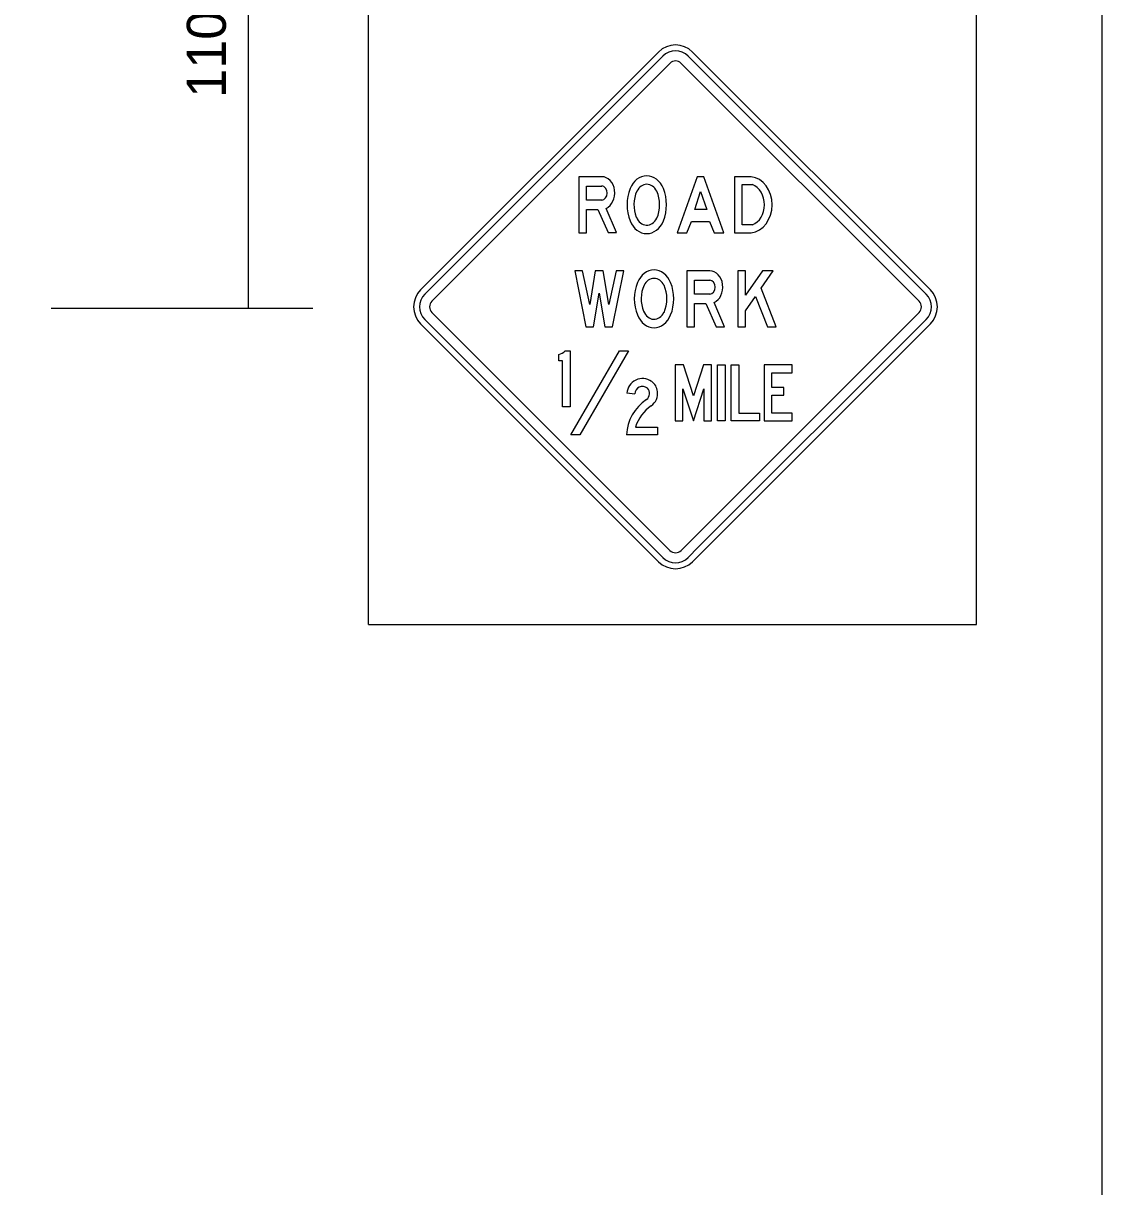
# Model space of a CAD drawing. Extents: x 21.7 to 29.1, y 5.9 to 16.2.
# Drawn here: x 27.437 to 29.094, y 7.653 to 9.44 of the extents above; entities that cross this region are included whole.
import ezdxf

# ---------------------------------------------------------------- set-up
doc = ezdxf.new("R2010")
doc.units = 0
for name, color, linetype in [('BORD-LINE', 7, 'Continuous'), ('C-SIGN-FACE-N', 7, 'Continuous'), ('DETL-DIMS', 7, 'Continuous'), ('DETL-LINE', 7, 'Continuous'), ('DETL-NOTE', 7, 'Continuous')]:
    doc.layers.add(name, color=color, linetype=linetype)

msp = doc.modelspace()

# ---------------------------------------------------------------- linework, layer by layer
at = {"layer": 'BORD-LINE'}
msp.add_lwpolyline([(21.7194, 16.2106), (29.0936, 16.2106), (29.0936, 5.8575), (21.7194, 5.8575)], close=True, dxfattribs=at)
at = {"layer": 'C-SIGN-FACE-N'}
for p, q in [((28.4129, 9.3962), (28.0475, 9.0309)), ((28.8304, 9.0309), (28.4651, 9.3962)), ((28.4915, 9.0242), (28.4915, 9.0242)), ((28.4129, 8.6133), (28.0475, 8.9787)), ((28.8304, 8.9787), (28.4651, 8.6133)), ((28.2596, 8.9216), (28.2596, 8.9314)), ((28.2596, 8.9216), (28.2596, 8.9314)), ((28.2596, 8.9216), (28.2596, 8.9314)), ((28.3763, 8.8708), (28.3642, 8.872)), ((28.3763, 8.8708), (28.3642, 8.872)), ((28.3763, 8.8708), (28.3642, 8.872)), ((28.3763, 8.8708), (28.3763, 8.8708)), ((28.3763, 8.8708), (28.3763, 8.8708)), ((28.3763, 8.8708), (28.3763, 8.8708)), ((28.4585, 8.6199), (28.474, 8.6354))]:
    msp.add_line(p, q, dxfattribs=at)
for points in [[(28.4194, 9.3897), (28.054, 9.0244)], [(28.8239, 9.0244), (28.4585, 9.3897)], [(28.0649, 9.0135), (28.4303, 9.3788)], [(28.4477, 9.3788), (28.813, 9.0135)], [(28.3256, 9.2047), (28.3022, 9.2047), (28.2906, 9.2047), (28.2906, 9.1186)], [(28.4913, 9.1359), (28.4985, 9.1186), (28.5133, 9.1186), (28.4823, 9.2047), (28.4723, 9.2047), (28.4413, 9.1186), (28.4562, 9.1186)], [(28.5552, 9.2047), (28.5295, 9.2047), (28.5295, 9.1186)], [(28.3256, 9.1688), (28.3022, 9.1688), (28.3022, 9.1903), (28.3256, 9.1903)], [(28.5414, 9.1307), (28.5414, 9.1925), (28.557, 9.1925)], [(28.2906, 9.1186), (28.3022, 9.1186), (28.3022, 9.1544), (28.3198, 9.1544), (28.3353, 9.1187)], [(28.3353, 9.1187), (28.3484, 9.1187), (28.3323, 9.1559)], [(28.4562, 9.1186), (28.4633, 9.1359), (28.4913, 9.1359)], [(28.5295, 9.1186), (28.5552, 9.1186)], [(28.557, 9.1307), (28.5414, 9.1307)], [(28.4915, 9.0601), (28.4681, 9.0601), (28.4565, 9.0601), (28.4565, 8.974)], [(28.4915, 9.0242), (28.4681, 9.0242), (28.4681, 9.0458), (28.4915, 9.0458)], [(28.4565, 8.974), (28.4681, 8.974), (28.4681, 9.0099), (28.4857, 9.0099), (28.5012, 8.9742), (28.5143, 8.9742), (28.4982, 9.0114)], [(28.4303, 8.6307), (28.0649, 8.9961)], [(28.813, 8.9961), (28.4477, 8.6307)], [(28.054, 8.9852), (28.4194, 8.6199)], [(28.474, 8.6354), (28.8239, 8.9852)], [(28.2694, 8.9371), (28.2773, 8.9371), (28.2773, 8.851), (28.2652, 8.851), (28.2652, 8.9216), (28.2596, 8.9216)], [(28.2694, 8.9371), (28.2773, 8.9371), (28.2773, 8.851), (28.2652, 8.851), (28.2652, 8.9216), (28.2596, 8.9216)], [(28.2694, 8.9371), (28.2773, 8.9371), (28.2773, 8.851), (28.2652, 8.851), (28.2652, 8.9216), (28.2596, 8.9216)], [(28.3775, 8.82), (28.4114, 8.82), (28.4114, 8.8079), (28.3636, 8.8079)], [(28.3775, 8.82), (28.4114, 8.82), (28.4114, 8.8079), (28.3636, 8.8079)], [(28.3775, 8.82), (28.4114, 8.82), (28.4114, 8.8079), (28.3636, 8.8079)], [(28.4585, 8.6199), (28.474, 8.6354)]]:
    msp.add_lwpolyline(points, dxfattribs=at)
for points in [[(28.4872, 9.1545), (28.4685, 9.1545), (28.4773, 9.182)], [(28.3595, 9.0601), (28.3477, 9.0601), (28.3364, 9.0085), (28.3281, 9.0601), (28.3157, 9.0601), (28.3073, 9.0085), (28.296, 9.0601), (28.2842, 9.0601), (28.3014, 8.974), (28.3132, 8.974), (28.3219, 9.0257), (28.3305, 8.974), (28.3423, 8.974)], [(28.5345, 8.974), (28.5463, 8.974), (28.5463, 8.9988), (28.5616, 9.0207), (28.5801, 8.974), (28.5937, 8.974), (28.5704, 9.0332), (28.5892, 9.0601), (28.5728, 9.0601), (28.5463, 9.0225), (28.5463, 9.0601), (28.5345, 9.0601)], [(28.3527, 8.9371), (28.3666, 8.9371), (28.2921, 8.8079), (28.2781, 8.8079)], [(28.3527, 8.9371), (28.3666, 8.9371), (28.2921, 8.8079), (28.2781, 8.8079)], [(28.3527, 8.9371), (28.3666, 8.9371), (28.2921, 8.8079), (28.2781, 8.8079)], [(28.4665, 8.8295), (28.4826, 8.879), (28.4826, 8.8295), (28.4944, 8.8295), (28.4944, 8.9156), (28.4819, 8.9156), (28.4665, 8.8679), (28.451, 8.9156), (28.4385, 8.9156), (28.4385, 8.8295), (28.4503, 8.8295), (28.4503, 8.879)], [(28.4665, 8.8295), (28.4826, 8.879), (28.4826, 8.8295), (28.4944, 8.8295), (28.4944, 8.9156), (28.4819, 8.9156), (28.4665, 8.8679), (28.451, 8.9156), (28.4385, 8.9156), (28.4385, 8.8295), (28.4503, 8.8295), (28.4503, 8.879)], [(28.4665, 8.8295), (28.4826, 8.879), (28.4826, 8.8295), (28.4944, 8.8295), (28.4944, 8.9156), (28.4819, 8.9156), (28.4665, 8.8679), (28.451, 8.9156), (28.4385, 8.9156), (28.4385, 8.8295), (28.4503, 8.8295), (28.4503, 8.879)], [(28.5036, 8.9156), (28.5154, 8.9156), (28.5154, 8.8295), (28.5036, 8.8295)], [(28.5036, 8.9156), (28.5154, 8.9156), (28.5154, 8.8295), (28.5036, 8.8295)], [(28.5036, 8.9156), (28.5154, 8.9156), (28.5154, 8.8295), (28.5036, 8.8295)], [(28.5246, 8.9156), (28.5364, 8.9156), (28.5364, 8.8415), (28.5678, 8.8415), (28.5678, 8.8295), (28.5246, 8.8295)], [(28.5246, 8.9156), (28.5364, 8.9156), (28.5364, 8.8415), (28.5678, 8.8415), (28.5678, 8.8295), (28.5246, 8.8295)], [(28.5246, 8.9156), (28.5364, 8.9156), (28.5364, 8.8415), (28.5678, 8.8415), (28.5678, 8.8295), (28.5246, 8.8295)], [(28.5869, 8.8415), (28.5869, 8.8691), (28.6055, 8.8691), (28.6055, 8.8811), (28.5869, 8.8811), (28.5869, 8.9035), (28.6183, 8.9035), (28.6183, 8.9156), (28.575, 8.9156), (28.575, 8.8295), (28.6183, 8.8295), (28.6183, 8.8415)], [(28.5869, 8.8415), (28.5869, 8.8691), (28.6055, 8.8691), (28.6055, 8.8811), (28.5869, 8.8811), (28.5869, 8.9035), (28.6183, 8.9035), (28.6183, 8.9156), (28.575, 8.9156), (28.575, 8.8295), (28.6183, 8.8295), (28.6183, 8.8415)], [(28.5869, 8.8415), (28.5869, 8.8691), (28.6055, 8.8691), (28.6055, 8.8811), (28.5869, 8.8811), (28.5869, 8.9035), (28.6183, 8.9035), (28.6183, 8.9156), (28.575, 8.9156), (28.575, 8.8295), (28.6183, 8.8295), (28.6183, 8.8415)]]:
    msp.add_lwpolyline(points, close=True, dxfattribs=at)
for centre, radius, start, end in [((28.439, 9.3701), 0.0369, 45, 135), ((28.439, 9.3701), 0.0277, 45, 135), ((28.439, 9.3701), 0.0123, 45, 135), ((28.0736, 9.0048), 0.0369, 135, 225), ((28.8043, 9.0048), 0.0369, 315, 45), ((28.0736, 9.0048), 0.0277, 135, 225), ((28.0736, 9.0048), 0.0123, 135, 225), ((28.8043, 9.0048), 0.0123, 315, 45), ((28.8043, 9.0048), 0.0277, 315, 45), ((28.253, 8.954), 0.0236, 286.2525, 314.1302), ((28.253, 8.954), 0.0236, 286.2525, 314.1302), ((28.253, 8.954), 0.0236, 286.2525, 314.1302), ((28.3883, 8.8705), 0.0241, 54.3694, 176.4795), ((28.3883, 8.8705), 0.0241, 54.3694, 176.4795), ((28.3883, 8.8705), 0.0241, 54.3694, 176.4795), ((28.3883, 8.8705), 0.012, 51.4666, 178.1909), ((28.3883, 8.8705), 0.012, 51.4666, 178.1909), ((28.3883, 8.8705), 0.012, 51.4666, 178.1909), ((28.391, 8.8735), 0.0201, 3.3316, 55.5862), ((28.391, 8.8735), 0.0201, 3.3316, 55.5862), ((28.391, 8.8735), 0.0201, 3.3316, 55.5862), ((28.3876, 8.8717), 0.0116, 306.1354, 44.8873), ((28.3876, 8.8717), 0.0116, 306.1354, 44.8873), ((28.3876, 8.8717), 0.0116, 306.1354, 44.8873), ((28.3899, 8.8709), 0.0215, 302.9934, 10.0902), ((28.3899, 8.8709), 0.0215, 302.9934, 10.0902), ((28.3899, 8.8709), 0.0215, 302.9934, 10.0902), ((28.4334, 8.8043), 0.0699, 123.8618, 177.0151), ((28.4334, 8.8043), 0.0699, 123.8618, 177.0151), ((28.4334, 8.8043), 0.0699, 123.8618, 177.0151), ((28.4384, 8.8006), 0.0639, 125.1387, 162.3655), ((28.4384, 8.8006), 0.0639, 125.1387, 162.3655), ((28.4384, 8.8006), 0.0639, 125.1387, 162.3655), ((28.439, 8.6394), 0.0277, 225, 315), ((28.439, 8.6394), 0.0123, 225, 315), ((28.439, 8.6394), 0.0369, 225, 315)]:
    msp.add_arc(centre, radius, start, end, dxfattribs=at)
for centre, major_axis, ratio, start_param, end_param in [((28.3253, 9.1796), (0, 0.0251), 0.813368, 3.487455, 6.269262), ((28.3948, 9.1711), (0, 0.0349), 0.812335, 5.167056, 7.399315), ((28.552, 9.1616), (0, 0.0432), 0.818392, 3.232708, 6.192058), ((28.3253, 9.1796), (0, 0.0108), 0.813368, 3.174143, 6.250457), ((28.4092, 9.1616), (0, 0.0549), 0.812335, 1.101522, 2.04007), ((28.3948, 9.1711), (0, 0.0219), 0.812335, 5.251232, 7.315139), ((28.3805, 9.1616), (0, 0.0549), 0.812335, 4.243115, 5.181663), ((28.5491, 9.1616), (0, 0.0324), 0.818392, 3.446507, 5.978271), ((28.4092, 9.1616), (0, 0.042), 0.812335, 1.053076, 2.040122), ((28.3805, 9.1616), (0, 0.042), 0.812335, 4.194619, 5.230159), ((28.3948, 9.1521), (0, 0.0349), 0.812335, 2.025463, 3.141593), ((28.3948, 9.1521), (0, 0.0219), 0.812335, 2.025521, 3.099563), ((28.3948, 9.1521), (0, 0.0219), 0.812335, 3.099563, 4.173604), ((28.3948, 9.1521), (0, 0.0349), 0.812335, 3.141593, 4.257722), ((28.406, 9.0266), (0, 0.0349), 0.812335, 5.167056, 7.399315), ((28.406, 9.0266), (0, 0.0219), 0.812335, 5.251232, 7.315139), ((28.4912, 9.035), (0, 0.0251), 0.813368, 3.487455, 6.268841), ((28.4912, 9.035), (0, 0.0108), 0.813368, 3.174143, 6.249461), ((28.4203, 9.0171), (0, 0.0549), 0.812335, 1.101522, 2.04007), ((28.4203, 9.0171), (0, 0.042), 0.812335, 1.053076, 2.040122), ((28.3917, 9.0171), (0, 0.042), 0.812335, 4.194619, 5.230159), ((28.3917, 9.0171), (0, 0.0549), 0.812335, 4.243115, 5.181663), ((28.406, 9.0076), (0, 0.0349), 0.812335, 2.025463, 3.141593), ((28.406, 9.0076), (0, 0.0219), 0.812335, 2.025521, 3.099563), ((28.406, 9.0076), (0, 0.0219), 0.812335, 3.099563, 4.173604), ((28.406, 9.0076), (0, 0.0349), 0.812335, 3.141593, 4.257722)]:
    msp.add_ellipse(centre, major_axis=major_axis, ratio=ratio, start_param=start_param, end_param=end_param, dxfattribs=at)
at = {"layer": 'DETL-DIMS'}
for p, q in [((27.7826, 9.8681), (27.7826, 9.0023)), ((27.8819, 9.0023), (27.48, 9.0023))]:
    msp.add_line(p, q, dxfattribs=at)
at = {"layer": 'DETL-LINE'}
for p, q in [((27.9676, 8.5166), (27.9676, 11.5089)), ((28.9014, 8.5166), (28.9014, 11.5089)), ((27.9676, 8.5166), (28.9014, 8.5166))]:
    msp.add_line(p, q, dxfattribs=at)

# ---------------------------------------------------------------- texts
at = {"layer": 'DETL-NOTE'}
msp.add_text("1100'", height=0.06, rotation=90, dxfattribs=at).set_placement((27.7484, 9.3258))

doc.saveas('drawing.dxf')
